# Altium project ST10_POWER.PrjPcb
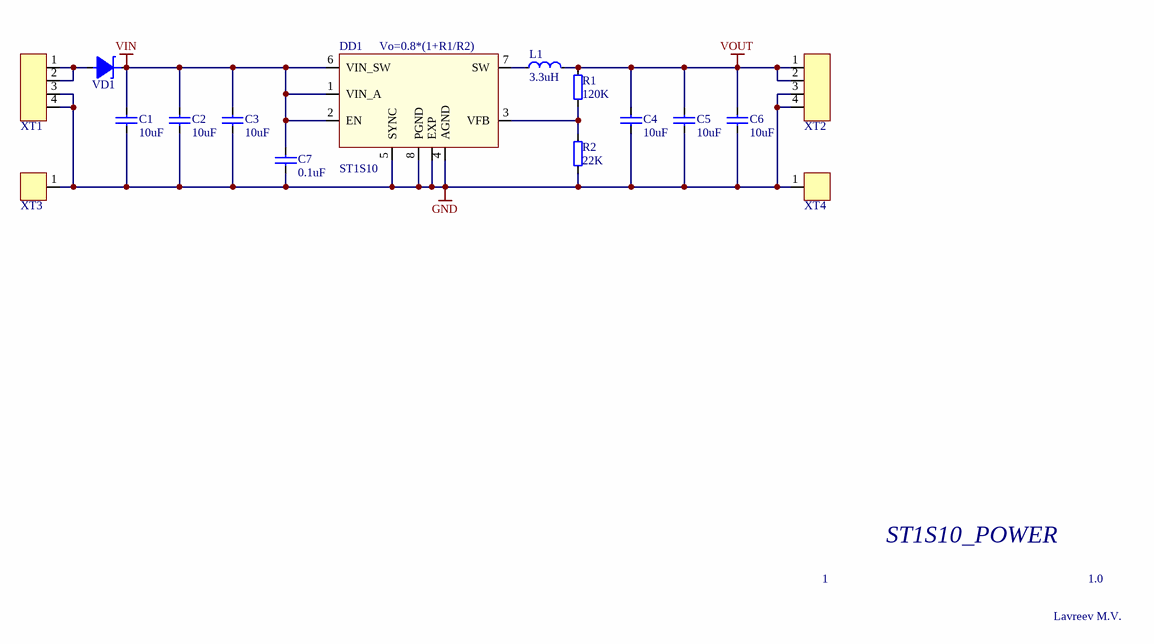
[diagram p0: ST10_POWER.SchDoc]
1 sheet, 16 parts. Net scope: global (net labels, ports and power ports of the same name join across sheets).
Board file: ST10_POWER.PcbDoc

## Sheet ST10_POWER.SchDoc
size A4

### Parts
DD1  ST1S10  [SO-8EPAD]
L1  3.3uH  [MSS7341]
R1  120K  [RES_0805]
R2  22K  [RES_0805]
VD1  SS24  [SMB]  (value not drawn)
XT1  *  [PLS-4_1]  (value not drawn)
XT2  *  [PLS-4_1]  (value not drawn)
XT3  *  [PLS-1_1]  (value not drawn)
XT4  *  [PLS-1_1]  (value not drawn)
С1  10uF  [CAP_CER_1206]
С2  10uF  [CAP_CER_0805]
С3  10uF  [CAP_CER_0805]
С4  10uF  [CAP_CER_0805]
С5  10uF  [CAP_CER_0805]
С6  10uF  [CAP_CER_1206]
С7  0.1uF  [CAP_CER_0805]

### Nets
GND: DD1.0(EXP) DD1.4(AGND) DD1.5(SYNC) DD1.8(PGND) R2.1 XT1.3 XT1.4 XT2.3 XT2.4 XT3.1 XT4.1 С1.1 С2.1 С3.1 С4.1 С5.1 С6.1 С7.1
VIN: DD1.1(VIN_A) DD1.2(EN) DD1.6(VIN_SW) VD1.2(C) С1.2 С2.2 С3.2 С7.2
VOUT: L1.1 R1.2 XT2.1 XT2.2 С4.2 С5.2 С6.2
NetDD1_3: DD1.3(VFB) R1.1 R2.2
NetDD1_7: DD1.7(SW) L1.2
NetVD1_1: VD1.1(A) XT1.1 XT1.2

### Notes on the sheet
- (near DD1) Vo=0.8*(1+R1/R2)
- ST1S10_POWER
- 1
- 1.0
- Lavreev M.V.

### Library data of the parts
DD1 = ST1S10: Step-Down3 A, 900 kHz, monolithic synchronous step-down regulator IC; Manufacturer: ST
L1 = L: Inductor
R1 R2 = RES_SMD: Chip Resistor; Tolerance: ±5%
VD1 = Diode Shottky: Diode
XT1 XT2 = PLS-4: Header Connector; Number of Positions: 4; Row Spacing: 2.54mm
XT3 XT4 = PLS-1: Header Connector; Number of Positions: 1; Row Spacing: 2.54mm
С1-С3 = CAP_CER: Fixed Ceramic Capacitor; Voltage: 25V; Tolerance: ±10%
С4-С7 = CAP_CER: Fixed Ceramic Capacitor; Voltage: 10V; Tolerance: ±10%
